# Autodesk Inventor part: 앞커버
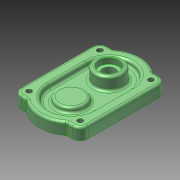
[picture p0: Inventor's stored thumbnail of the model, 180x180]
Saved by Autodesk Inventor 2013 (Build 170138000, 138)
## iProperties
Created: 2013-07
Part Number: 앞커버
Document SubType Name: Modeling
Designer: 한국산업디자인학원
Density: 1 g/cm^3
Mass: 127.306 g
Surface Area: 321.226 cm^2
Volume: 127.306 cm^3
Material: 알루미늄 6061
Author: 한국산업디자인학원
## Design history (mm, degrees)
sketch "스케치1"
  geometry: L1 (-28.5, -82.106)-(-28.5, -34.106) reference; L2 (28.5, -34.106)-(28.5, -82.106) reference; L3 (-42.5, -103.106)-(-42.5, -13.106) reference; L4 (-26.325, -113.106)-(-32.5, -113.106) reference; L5 (32.5, -113.106)-(26.325, -113.106) reference; L6 (42.5, -13.106)-(42.5, -103.106) reference; L7 (26.325, -3.106)-(32.5, -3.106) reference; L8 (-32.5, -3.106)-(-26.325, -3.106) reference; C1 r 4.5 at (-32.5, -13.106) reference; C2 r 4.5 at (32.5, -103.106) reference; C3 r 4.5 at (-32.5, -103.106) reference; C4 r 4.5 at (32.5, -13.106) reference; A1 r 28.5 centre (0, -82.106) between (-28.5, -82.106) and (28.5, -82.106) reference; A2 r 28.5 centre (0, -34.106) between (28.5, -34.106) and (-28.5, -34.106) reference; A3 r 10 centre (-32.5, -103.106) between (-42.5, -103.106) and (-32.5, -113.106) reference; A4 r 3 centre (-26.325, -116.106) between (-24.488, -113.734) and (-26.325, -113.106) reference; A5 r 40 centre (0, -82.106) between (-24.488, -113.734) and (24.488, -113.734) reference; A6 r 3 centre (26.325, -116.106) between (26.325, -113.106) and (24.488, -113.734) reference; A7 r 10 centre (32.5, -103.106) between (32.5, -113.106) and (42.5, -103.106) reference; A8 r 10 centre (32.5, -13.106) between (42.5, -13.106) and (32.5, -3.106) reference; A9 r 3 centre (26.325, -0.106) between (24.488, -2.478) and (26.325, -3.106) reference; A10 r 40 centre (0, -34.106) between (24.488, -2.478) and (-24.488, -2.478) reference; A11 r 3 centre (-26.325, -0.106) between (-26.325, -3.106) and (-24.488, -2.478) reference; A12 r 10 centre (-32.5, -13.106) between (-32.5, -3.106) and (-42.5, -13.106) reference
extrude "돌출1" new body sketch "스케치1" distance "d0" = 15; taper "d1" = 0 deg
sketch "스케치2"
  geometry: L1 (-28.5, -34.106)-(-28.5, -82.106) reference; L2 (28.5, -82.106)-(28.5, -34.106) reference; A1 r 28.5 centre (0, -34.106) between (28.5, -34.106) and (-28.5, -34.106) reference; A2 r 28.5 centre (0, -82.106) between (-28.5, -82.106) and (28.5, -82.106) reference
extrude "돌출2" join sketch "스케치2" distance "d2" = 5; taper "d3" = 0 deg
sketch "스케치11"
  geometry: L1 (-103.106, 15)-(-13.106, 15) reference; L2 (-82.106, -5)-(-110.606, -5) reference; L3 (-82.106, -5)-(-82.106, 15); L4 (-96.106, -5)-(-96.106, 8); L5 (-96.106, 8)-(-92.106, 8); L6 (-90.106, 10)-(-82.106, 10); A1 r 2 centre (-90.106, 8) between (-90.106, 10) and (-92.106, 8); 1 further point
  constraints: 8 end point, 4 point on line, 2 parallel, 2 perpendicular, 2 point on circle, 1 centre point, 1 tangent, 1 vertical alignment
  dimensions: "d77" = 13 distance of L4.start L4.end; "d78" = 2 distance between parallel lines of L6 L5; "d79" = 28 diameter of L4 L3; "d80" = 20 diameter of L5.end L3
revolve "회전1" sketch "스케치11" stored, may be unused: angle "d81" = 90 deg
sketch "스케치8"
  geometry: L1 (28, -82.106)-(28, -34.106); L2 (-28, -82.106)-(-28, -34.106); C1 r 17.5 at (0, -82.106); C2 r 17.5 at (0, -34.106); A1 r 28 centre (0, -82.106) between (28, -82.106) and (-28, -82.106); A2 r 28 centre (0, -34.106) between (-17.161, -56.231) and (17.161, -56.231); A3 r 40 centre (0, -34.106) between (24.488, -2.478) and (-24.488, -2.478) reference; A4 r 40 centre (0, -82.106) between (-24.488, -113.734) and (24.488, -113.734) reference
  constraints: 6 point on circle, 4 centre point, 4 end point, 3 concentric, 2 equal radius, 2 parallel, 1 coincident, 1 tangent, 1 vertical
  dimensions: "d43" = 56 diameter of A1; "d44" = 35 diameter of C1
extrude "돌출5" cut sketch "스케치8" distance "d47" = 6; taper "d48" = 0 deg
sketch "스케치12"
  geometry: C1 r 17.5 at (0, 0) reference; 1 further point
extrude "돌출7" join sketch "스케치12" distance "d87" = 10; taper "d88" = 0 deg
fillet "모깎기1" dims "d49" = 3
fillet "모깎기2" dims "d50" = 3, "d51" = 0.3
chamfer "모따기1" distance "d52" = 1; stored, may be unused: second distance "d53" = 2, angle "d54" = 45 deg
sketch "스케치13"
  geometry: L1 (-5.606, -5)-(-34.106, -5) reference; L2 (-48.606, 25)-(-19.606, 25) reference; L3 (-34.106, -5)-(-34.106, 25); L4 (-20.106, -5)-(-20.106, 8); L5 (-20.106, 8)-(-26.035, 8); L6 (-26.035, 8)-(-26.035, 17.7); L7 (-26.035, 17.7)-(-21.906, 17.7); L8 (-21.606, 18)-(-21.606, 25); L9 (-96.106, 8)-(-68.106, 8) reference; A1 r 0.3 centre (-21.906, 18) between (-21.906, 17.7) and (-21.606, 18); 3 further points
  constraints: 12 end point, 4 point on line, 3 parallel, 2 perpendicular, 2 point on circle, 2 tangent, 1 centre point, 1 collinear, 1 midpoint, 1 other
  dimensions: "d89" = 28 distance of L9.end L9.start (derived); "d90" = 28 diameter of L4 L3 (= d89); "d91" = 1 distance from line of L6 point (-27.035, 59); "d93" = 7.3 distance between parallel lines of L7 L2; "d94" = 25 diameter of L8 L3; "d98" = 0.3 radius of A1
revolve "회전2" sketch "스케치13" stored, may be unused: angle "d92" = 90 deg
chamfer "모따기2" distance "d95" = 0.7; stored, may be unused: second distance "d96" = 2, angle "d97" = 30 deg
sketch "스케치14"
  geometry: C1 r 4.5 at (-32.5, -13.106) reference; C2 r 4.5 at (32.5, -13.106) reference; C3 r 4.5 at (32.5, -103.106) reference; C4 r 4.5 at (-32.5, -103.106) reference; 1 further point
hole "구멍7" sketch "스케치14" at (-32.5, -13.106), (32.5, -13.106), (32.5, -103.106), (-32.5, -103.106) diameter "d99" = 6.647; stored, may be unused: countersink angle "d103" = 90 deg, drill point angle "d105" = 118 deg; dims "d100" = 20, "d101" = 4, "d102" = 2, "d104" = 8
node "솔리드1"
node "참조10"
node "참조11"
node "참조12"
node "참조13"
node "참조14"
node "참조19"
node "참조20"
node "참조21"
node "참조22"
